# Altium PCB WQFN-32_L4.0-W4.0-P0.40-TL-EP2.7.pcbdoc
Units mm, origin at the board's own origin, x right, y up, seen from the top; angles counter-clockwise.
Board outline 17.55 x 17.12 mm, 2 copper layers (Top Layer, Bottom Layer), stack 0 mm thick; 1 components, 0 nets, 33 pads, 0 vias.
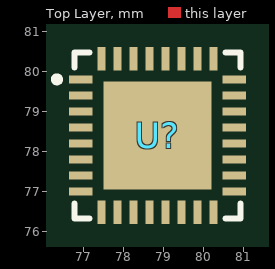
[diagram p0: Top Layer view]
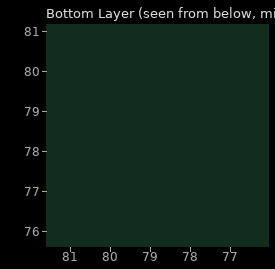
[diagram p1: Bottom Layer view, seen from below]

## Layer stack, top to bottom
Top Layer: signal copper (thickness not stored)
Bottom Layer: signal copper (thickness not stored)

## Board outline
87.4,69.85 69.85,69.85 69.85,86.97 87.4,86.97

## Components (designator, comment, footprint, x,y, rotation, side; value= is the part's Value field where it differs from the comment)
U? "" WQFN-32_L4.0-W4.0-P0.40-TL-EP2.7 78.84,78.41 r0 top

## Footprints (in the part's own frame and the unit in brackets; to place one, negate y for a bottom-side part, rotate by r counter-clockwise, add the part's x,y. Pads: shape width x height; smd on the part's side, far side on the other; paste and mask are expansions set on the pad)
WQFN-32_L4.0-W4.0-P0.40-TL-EP2.7 [mm]
  rect 0.585x0.2 smd paste-100 mask+0.051: 1(-1.917,1.4) 2(-1.917,1) 3(-1.917,0.6) 4(-1.917,0.2) 5(-1.917,-0.2) 6(-1.917,-0.6) 7(-1.917,-1) 8(-1.917,-1.4) 17(1.917,-1.4) 18(1.917,-1) 19(1.917,-0.6) 20(1.917,-0.2) 21(1.917,0.2) 22(1.917,0.6) 23(1.917,1) 24(1.917,1.4)
  rect 0.2x0.585 smd paste-100 mask+0.051: 9(-1.4,-1.918) 10(-1,-1.918) 11(-0.6,-1.918) 12(-0.2,-1.918) 13(0.2,-1.918) 14(0.6,-1.918) 15(1,-1.918) 16(1.4,-1.918) 25(1.4,1.918) 26(1,1.918) 27(0.6,1.918) 28(0.2,1.918) 29(-0.2,1.918) 30(-0.6,1.918) 31(-1,1.918) 32(-1.4,1.918)
  rect 2.7x2.7 smd paste-100 mask+0.051: 33(0,0)
  silkscreen extent -2.58,-2.08 2.08,2.08

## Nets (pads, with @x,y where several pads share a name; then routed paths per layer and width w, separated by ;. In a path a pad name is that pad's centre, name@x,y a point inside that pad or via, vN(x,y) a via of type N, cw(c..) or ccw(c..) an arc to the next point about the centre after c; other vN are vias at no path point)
pads on no net: U?.1 U?.2 U?.3 U?.4 U?.5 U?.6 U?.7 U?.8 U?.9 U?.10 U?.11 U?.12 U?.13 U?.14 U?.15 U?.16 U?.17 U?.18 U?.19 U?.20 U?.21 U?.22 U?.23 U?.24 U?.25 U?.26 U?.27 U?.28 U?.29 U?.30 U?.31 U?.32 U?.33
